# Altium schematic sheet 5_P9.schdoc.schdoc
size 309 x 223 mm; Symbol: A4_Schematic_0605; Device: A4_Schematic_0605; @Project Name: MDIO-Board_Rev_01(0124); @Page Count: 10; @Update Date: 2024-05-25; @Create Date: 2024-05-19; @Schematic Name: Schematic1; @Page No: 9; @Page Name: P9
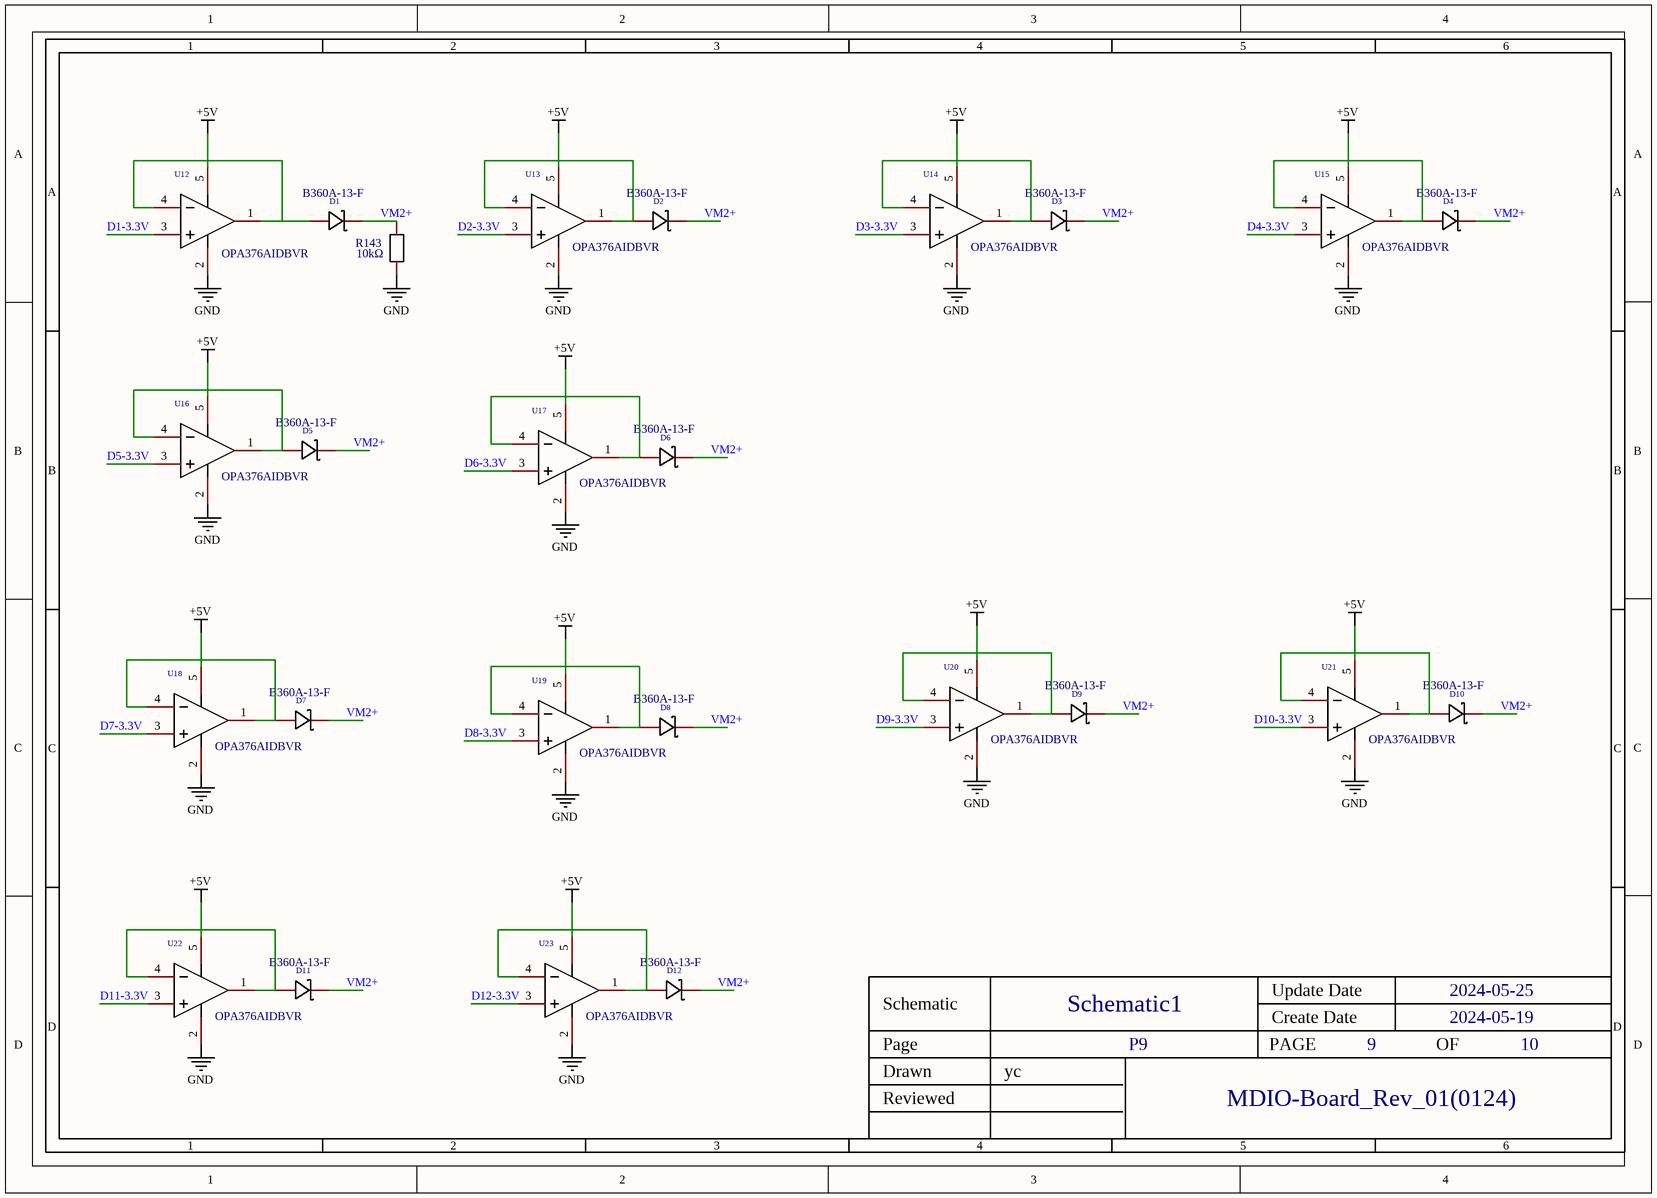
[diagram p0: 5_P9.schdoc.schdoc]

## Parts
D1  B360A-13-F  [SMA_L4.4-W2.6-LS5.0-RD]
D2  B360A-13-F  [SMA_L4.4-W2.6-LS5.0-RD]
D3  B360A-13-F  [SMA_L4.4-W2.6-LS5.0-RD]
D4  B360A-13-F  [SMA_L4.4-W2.6-LS5.0-RD]
D5  B360A-13-F  [SMA_L4.4-W2.6-LS5.0-RD]
D6  B360A-13-F  [SMA_L4.4-W2.6-LS5.0-RD]
D7  B360A-13-F  [SMA_L4.4-W2.6-LS5.0-RD]
D8  B360A-13-F  [SMA_L4.4-W2.6-LS5.0-RD]
D9  B360A-13-F  [SMA_L4.4-W2.6-LS5.0-RD]
D10  B360A-13-F  [SMA_L4.4-W2.6-LS5.0-RD]
D11  B360A-13-F  [SMA_L4.4-W2.6-LS5.0-RD]
D12  B360A-13-F  [SMA_L4.4-W2.6-LS5.0-RD]
R143  10kΩ  [R0603]
U12  OPA376AIDBVR  [SOT-23-5_L3.0-W1.7-P0.95-LS2.8-BR]
U13  OPA376AIDBVR  [SOT-23-5_L3.0-W1.7-P0.95-LS2.8-BR]
U14  OPA376AIDBVR  [SOT-23-5_L3.0-W1.7-P0.95-LS2.8-BR]
U15  OPA376AIDBVR  [SOT-23-5_L3.0-W1.7-P0.95-LS2.8-BR]
U16  OPA376AIDBVR  [SOT-23-5_L3.0-W1.7-P0.95-LS2.8-BR]
U17  OPA376AIDBVR  [SOT-23-5_L3.0-W1.7-P0.95-LS2.8-BR]
U18  OPA376AIDBVR  [SOT-23-5_L3.0-W1.7-P0.95-LS2.8-BR]
U19  OPA376AIDBVR  [SOT-23-5_L3.0-W1.7-P0.95-LS2.8-BR]
U20  OPA376AIDBVR  [SOT-23-5_L3.0-W1.7-P0.95-LS2.8-BR]
U21  OPA376AIDBVR  [SOT-23-5_L3.0-W1.7-P0.95-LS2.8-BR]
U22  OPA376AIDBVR  [SOT-23-5_L3.0-W1.7-P0.95-LS2.8-BR]
U23  OPA376AIDBVR  [SOT-23-5_L3.0-W1.7-P0.95-LS2.8-BR]

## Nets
+5V: U12.5(V+) U13.5(V+) U14.5(V+) U15.5(V+) U16.5(V+) U17.5(V+) U18.5(V+) U19.5(V+) U20.5(V+) U21.5(V+) U22.5(V+) U23.5(V+)
GND: R143.1 U12.2(V-) U13.2(V-) U14.2(V-) U15.2(V-) U16.2(V-) U17.2(V-) U18.2(V-) U19.2(V-) U20.2(V-) U21.2(V-) U22.2(V-) U23.2(V-)
D1-3.3V: U12.3(IN+)
D2-3.3V: U13.3(IN+)
D3-3.3V: U14.3(IN+)
D4-3.3V: U15.3(IN+)
D5-3.3V: U16.3(IN+)
D6-3.3V: U17.3(IN+)
D7-3.3V: U18.3(IN+)
D8-3.3V: U19.3(IN+)
D9-3.3V: U20.3(IN+)
D10-3.3V: U21.3(IN+)
D11-3.3V: U22.3(IN+)
D12-3.3V: U23.3(IN+)
VM2+: D1.1(K) D2.1(K) D3.1(K) D4.1(K) D5.1(K) D6.1(K) D7.1(K) D8.1(K) D9.1(K) D10.1(K) D11.1(K) D12.1(K) R143.2
NetD1_2: D1.2(A) U12.1(OUT) U12.4(IN-)
NetD2_2: D2.2(A) U13.1(OUT) U13.4(IN-)
NetD3_2: D3.2(A) U14.1(OUT) U14.4(IN-)
NetD4_2: D4.2(A) U15.1(OUT) U15.4(IN-)
NetD5_2: D5.2(A) U16.1(OUT) U16.4(IN-)
NetD6_2: D6.2(A) U17.1(OUT) U17.4(IN-)
NetD7_2: D7.2(A) U18.1(OUT) U18.4(IN-)
NetD8_2: D8.2(A) U19.1(OUT) U19.4(IN-)
NetD9_2: D9.2(A) U20.1(OUT) U20.4(IN-)
NetD10_2: D10.2(A) U21.1(OUT) U21.4(IN-)
NetD11_2: D11.2(A) U22.1(OUT) U22.4(IN-)
NetD12_2: D12.2(A) U23.1(OUT) U23.4(IN-)

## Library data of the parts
D1-D12 = B360A-13-F: Manufacturer: DIODES(美台); Add into BOM: yes; Forward Voltage (Vf@If): 700mV@3A; Reverse Voltage (Vr): 60V; Average Rectified Current (Io): 3A; Reverse Leakage Current (Ir): 500uA@60V; Description: Forward Voltage (Vf@If):700mV@3A Reverse Voltage (Vr):60V Average Rectified Current (Io):3A Reverse Leakage Current (Ir):500uA@60V
R143 = SCR0603J10K: Manufacturer: VO(翔胜); Add into BOM: yes; Tolerance: ±5%; Description: Type:Thick Film Resistors Resistance: Tolerance:±5% Tolerance:±5% Power(Watts): Overload Voltage (Max): Operating Temperature Range:-55℃~+155℃ Operating Temperature Range:-55℃~+155℃
U12-U23 = OPA376AIDBVR: Manufacturer: TI(德州仪器); Add into BOM: yes; Number of Circuits: 单路; Gain Bandwidth Product(GBP): 5.5MHz; Current - Input Bias(Ib): 0.2pA; Slew Rate(SR): 2V/us; Output Current: 50mA; Supply Current: 760uA; Description: Number of Circuits:单路 Gain Bandwidth Product(GBP):5.5MHz Current - Input Bias(Ib):0.2pA Slew Rate(SR):2V/us Output Current:50mA Output Type:- Rail to Rail:- Supply Current:760uA Operating Temperature:-40℃~+125℃ Operating Temperature:-40℃~+125℃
